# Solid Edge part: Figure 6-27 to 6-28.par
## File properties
Author: CADCIM
Template: Normal.par
Last saved by: CADCIM
Revision: 6
Application: Solid Edge
Accuracy: 0.99
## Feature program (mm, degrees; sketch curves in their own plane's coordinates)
sketch for "unnamed Protrusion 1" plane through (0, 0, 0) normal (0, 0, 1) x-axis (1, 0, 0)
  line (-52.1766, -31.6987) -> (52.1766, -31.6987)
  line (52.1766, -31.6987) -> (52.1766, 31.6987)
  line (52.1766, 31.6987) -> (-52.1766, 31.6987)
  line (-52.1766, 31.6987) -> (-52.1766, -31.6987)
extrude "unnamed Protrusion 1" add finite 57.15 along +normal
sketch for "ExtrudedCutout_1" plane through (0, 0, 57.15) normal (0, 0, 1) x-axis (0, 1, 0)
  line (-31.6987, 0) -> (8.7819, 0)
  line (8.7819, 0) -> (8.7819, -52.1766)
extrude "ExtrudedCutout_1" cut finite 41.275 along -normal
fillet "Round_7" radius 5
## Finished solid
Body 1: solid body, 18 faces, 45 edges, 29 vertices.
  Faces by surface: plane 9, spline 6, cylinder 3
  Edges by curve: line 24, curve on surface 15, circle 3, spline 3
Bounding box of the edges (mm; curved faces can reach further): 104.353 x 63.397 x 57.150, from (-52.1766, -31.6987, 0) to (52.1766, 31.6987, 57.15).
Cylindrical faces by radius (mm): R5 x3
Planar faces by outward normal: +x 2, +y 1, +z 2, -x 1, -y 2, -z 1
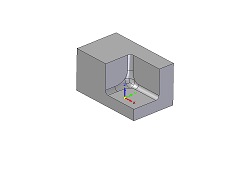
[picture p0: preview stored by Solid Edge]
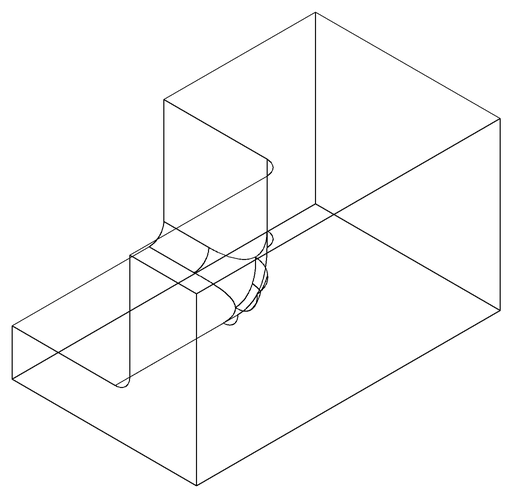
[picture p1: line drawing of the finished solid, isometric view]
